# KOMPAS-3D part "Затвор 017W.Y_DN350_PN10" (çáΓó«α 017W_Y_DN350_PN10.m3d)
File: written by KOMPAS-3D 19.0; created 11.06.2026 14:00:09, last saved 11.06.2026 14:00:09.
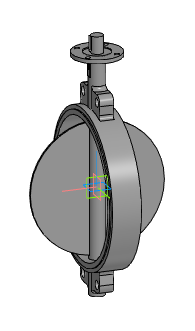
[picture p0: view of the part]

Document properties: Автор: Евгений; Полное имя файла: Z:\3.Личные\kachalov\001_3d для проектировщиков\x.x Тип 017W.Y(S) Затвор дисковый поворотный межфланцевый\_stp_Затвор 017W.Y_DN50-DN350\Затвор 017W_Y_DN350_PN10.m3d

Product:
- Part/product: Затвор 017W.Y_DN350_PN10

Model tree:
1. Операция без истории:1  (labels: Затвор 017W.Y_DN350_PN10)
